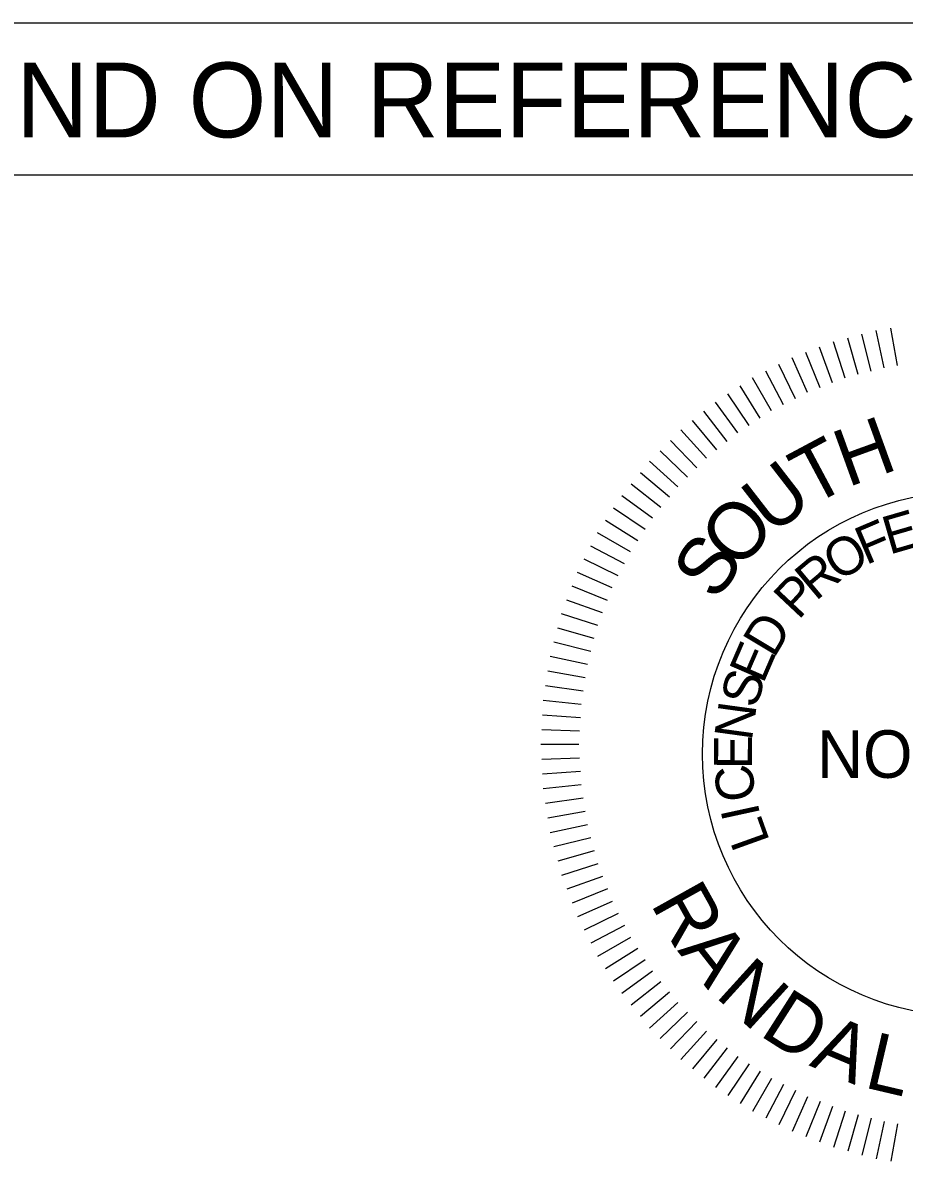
# Model space of a CAD drawing. Extents: x 1964377 to 1966966, y 1116414 to 1123213.
# Drawn here: x 1966782.8 to 1966865.3, y 1120286.7 to 1120393.2 of the extents above; entities that cross this region are included whole.
import ezdxf

# ---------------------------------------------------------------- set-up
doc = ezdxf.new("R2010")
doc.units = 0
doc.layers.add('RD_Sketch1', color=7, linetype='Continuous')
doc.layers.add('RD_TX_PEShield', color=7, linetype='Continuous')

msp = doc.modelspace()

# ---------------------------------------------------------------- linework, layer by layer
at = {"layer": 'RD_Sketch1'}
msp.add_lwpolyline([(1966615.77, 1120393.19), (1966916.19, 1120393.19), (1966916.19, 1120378.93), (1966615.77, 1120378.93)], close=True, dxfattribs=at)
at = {"layer": 'RD_TX_PEShield'}
for p, q in [((1966862.19, 1120360.61), (1966861.33, 1120364.06)), ((1966862.19, 1120360.61), (1966861.33, 1120364.06)), ((1966863.4, 1120360.93), (1966862.66, 1120364.41)), ((1966863.4, 1120360.93), (1966862.66, 1120364.41)), ((1966864.65, 1120361.13), (1966864.03, 1120364.63)), ((1966864.65, 1120361.13), (1966864.03, 1120364.63)), ((1966859.76, 1120359.96), (1966858.66, 1120363.34)), ((1966859.76, 1120359.96), (1966858.66, 1120363.34)), ((1966860.98, 1120360.28), (1966860, 1120363.7)), ((1966860.98, 1120360.28), (1966860, 1120363.7)), ((1966857.41, 1120359.06), (1966856.08, 1120362.35)), ((1966857.41, 1120359.06), (1966856.08, 1120362.35)), ((1966858.59, 1120359.51), (1966857.37, 1120362.85)), ((1966858.59, 1120359.51), (1966857.37, 1120362.85)), ((1966855.12, 1120358.03), (1966853.56, 1120361.23)), ((1966855.12, 1120358.03), (1966853.56, 1120361.23)), ((1966856.24, 1120358.6), (1966854.79, 1120361.86)), ((1966856.24, 1120358.6), (1966854.79, 1120361.86)), ((1966852.88, 1120356.89), (1966851.1, 1120359.97)), ((1966852.88, 1120356.89), (1966851.1, 1120359.97)), ((1966854, 1120357.46), (1966852.33, 1120360.6)), ((1966854, 1120357.46), (1966852.33, 1120360.6)), ((1966851.82, 1120356.21), (1966849.94, 1120359.22)), ((1966851.82, 1120356.21), (1966849.94, 1120359.22)), ((1966849.71, 1120354.84), (1966847.62, 1120357.72)), ((1966849.71, 1120354.84), (1966847.62, 1120357.72)), ((1966850.77, 1120355.52), (1966848.78, 1120358.47)), ((1966850.77, 1120355.52), (1966848.78, 1120358.47)), ((1966848.73, 1120354.04), (1966846.54, 1120356.85)), ((1966848.73, 1120354.04), (1966846.54, 1120356.85)), ((1966847.76, 1120353.25), (1966845.47, 1120355.98)), ((1966847.76, 1120353.25), (1966845.47, 1120355.98)), ((1966846.78, 1120352.46), (1966844.4, 1120355.11)), ((1966846.78, 1120352.46), (1966844.4, 1120355.11)), ((1966845.89, 1120351.57), (1966843.42, 1120354.13)), ((1966845.89, 1120351.57), (1966843.42, 1120354.13)), ((1966845, 1120350.68), (1966842.44, 1120353.15)), ((1966845, 1120350.68), (1966842.44, 1120353.15)), ((1966844.11, 1120349.79), (1966841.47, 1120352.18)), ((1966844.11, 1120349.79), (1966841.47, 1120352.18)), ((1966843.32, 1120348.82), (1966840.6, 1120351.1)), ((1966843.32, 1120348.82), (1966840.6, 1120351.1)), ((1966842.53, 1120347.84), (1966839.73, 1120350.03)), ((1966842.53, 1120347.84), (1966839.73, 1120350.03)), ((1966841.74, 1120346.86), (1966838.86, 1120348.95)), ((1966841.74, 1120346.86), (1966838.86, 1120348.95)), ((1966841.05, 1120345.81), (1966838.1, 1120347.8)), ((1966841.05, 1120345.81), (1966838.1, 1120347.8)), ((1966840.37, 1120344.75), (1966837.35, 1120346.64)), ((1966840.37, 1120344.75), (1966837.35, 1120346.64)), ((1966839.68, 1120343.7), (1966836.6, 1120345.48)), ((1966839.68, 1120343.7), (1966836.6, 1120345.48)), ((1966839.11, 1120342.58), (1966835.97, 1120344.25)), ((1966839.11, 1120342.58), (1966835.97, 1120344.25)), ((1966838.54, 1120341.46), (1966835.35, 1120343.02)), ((1966838.54, 1120341.46), (1966835.35, 1120343.02)), ((1966837.97, 1120340.34), (1966834.72, 1120341.78)), ((1966837.97, 1120340.34), (1966834.72, 1120341.78)), ((1966837.52, 1120339.16), (1966834.22, 1120340.49)), ((1966837.52, 1120339.16), (1966834.22, 1120340.49)), ((1966837.07, 1120337.99), (1966833.73, 1120339.2)), ((1966837.07, 1120337.99), (1966833.73, 1120339.2)), ((1966836.62, 1120336.81), (1966833.23, 1120337.91)), ((1966836.62, 1120336.81), (1966833.23, 1120337.91)), ((1966836.29, 1120335.6), (1966832.87, 1120336.58)), ((1966836.29, 1120335.6), (1966832.87, 1120336.58)), ((1966835.97, 1120334.38), (1966832.52, 1120335.25)), ((1966835.97, 1120334.38), (1966832.52, 1120335.25)), ((1966835.64, 1120333.17), (1966832.16, 1120333.91)), ((1966835.64, 1120333.17), (1966832.16, 1120333.91)), ((1966835.44, 1120331.93), (1966831.94, 1120332.54)), ((1966835.44, 1120331.93), (1966831.94, 1120332.54)), ((1966835.25, 1120330.69), (1966831.73, 1120331.18)), ((1966835.25, 1120330.69), (1966831.73, 1120331.18)), ((1966835.05, 1120329.44), (1966831.51, 1120329.82)), ((1966835.05, 1120329.44), (1966831.51, 1120329.82)), ((1966834.99, 1120328.19), (1966831.44, 1120328.43)), ((1966834.99, 1120328.19), (1966831.44, 1120328.43)), ((1966834.92, 1120326.93), (1966831.37, 1120327.06)), ((1966834.92, 1120326.93), (1966831.37, 1120327.06)), ((1966834.85, 1120325.68), (1966831.29, 1120325.68)), ((1966834.85, 1120325.68), (1966831.29, 1120325.68)), ((1966834.92, 1120324.42), (1966831.37, 1120324.29)), ((1966834.92, 1120324.42), (1966831.37, 1120324.29)), ((1966834.99, 1120323.16), (1966831.44, 1120322.92)), ((1966834.99, 1120323.16), (1966831.44, 1120322.92)), ((1966835.05, 1120321.91), (1966831.51, 1120321.54)), ((1966835.05, 1120321.91), (1966831.51, 1120321.54)), ((1966835.25, 1120320.67), (1966831.73, 1120320.17)), ((1966835.25, 1120320.67), (1966831.73, 1120320.17)), ((1966835.44, 1120319.42), (1966831.94, 1120318.81)), ((1966835.44, 1120319.42), (1966831.94, 1120318.81)), ((1966835.64, 1120318.18), (1966832.16, 1120317.44)), ((1966835.64, 1120318.18), (1966832.16, 1120317.44)), ((1966835.97, 1120316.97), (1966832.52, 1120316.11)), ((1966835.97, 1120316.97), (1966832.52, 1120316.11)), ((1966836.29, 1120315.75), (1966832.87, 1120314.77)), ((1966836.29, 1120315.75), (1966832.87, 1120314.77)), ((1966836.62, 1120314.54), (1966833.23, 1120313.44)), ((1966837.07, 1120313.36), (1966833.73, 1120312.15)), ((1966837.07, 1120313.36), (1966833.73, 1120312.15)), ((1966837.52, 1120312.19), (1966834.22, 1120310.86)), ((1966837.52, 1120312.19), (1966834.22, 1120310.86)), ((1966837.97, 1120311.01), (1966834.72, 1120309.57)), ((1966837.97, 1120311.01), (1966834.72, 1120309.57)), ((1966838.54, 1120309.89), (1966835.35, 1120308.33)), ((1966838.54, 1120309.89), (1966835.35, 1120308.33)), ((1966839.11, 1120308.77), (1966835.97, 1120307.1)), ((1966839.11, 1120308.77), (1966835.97, 1120307.1)), ((1966839.68, 1120307.65), (1966836.6, 1120305.87)), ((1966839.68, 1120307.65), (1966836.6, 1120305.87)), ((1966840.37, 1120306.6), (1966837.35, 1120304.71)), ((1966840.37, 1120306.6), (1966837.35, 1120304.71)), ((1966841.05, 1120305.54), (1966838.1, 1120303.56)), ((1966841.05, 1120305.54), (1966838.1, 1120303.56)), ((1966841.74, 1120304.49), (1966838.86, 1120302.4)), ((1966841.74, 1120304.49), (1966838.86, 1120302.4)), ((1966842.53, 1120303.51), (1966839.73, 1120301.32)), ((1966842.53, 1120303.51), (1966839.73, 1120301.32)), ((1966843.32, 1120302.53), (1966840.6, 1120300.25)), ((1966843.32, 1120302.53), (1966840.6, 1120300.25)), ((1966844.11, 1120301.56), (1966841.47, 1120299.17)), ((1966844.11, 1120301.56), (1966841.47, 1120299.17)), ((1966845, 1120300.67), (1966842.44, 1120298.2)), ((1966845, 1120300.67), (1966842.44, 1120298.2)), ((1966845.89, 1120299.78), (1966843.42, 1120297.22)), ((1966845.89, 1120299.78), (1966843.42, 1120297.22)), ((1966846.78, 1120298.89), (1966844.4, 1120296.24)), ((1966846.78, 1120298.89), (1966844.4, 1120296.24)), ((1966847.76, 1120298.1), (1966845.47, 1120295.37)), ((1966847.76, 1120298.1), (1966845.47, 1120295.37)), ((1966848.73, 1120297.31), (1966846.54, 1120294.5)), ((1966848.73, 1120297.31), (1966846.54, 1120294.5)), ((1966849.71, 1120296.51), (1966847.62, 1120293.63)), ((1966849.71, 1120296.51), (1966847.62, 1120293.63)), ((1966850.77, 1120295.83), (1966848.78, 1120292.88)), ((1966850.77, 1120295.83), (1966848.78, 1120292.88)), ((1966851.82, 1120295.14), (1966849.94, 1120292.13)), ((1966851.82, 1120295.14), (1966849.94, 1120292.13)), ((1966852.88, 1120294.46), (1966851.1, 1120291.38)), ((1966852.88, 1120294.46), (1966851.1, 1120291.38)), ((1966854, 1120293.89), (1966852.33, 1120290.75)), ((1966854, 1120293.89), (1966852.33, 1120290.75)), ((1966855.12, 1120293.32), (1966853.56, 1120290.12)), ((1966855.12, 1120293.32), (1966853.56, 1120290.12)), ((1966856.24, 1120292.75), (1966854.79, 1120289.49)), ((1966856.24, 1120292.75), (1966854.79, 1120289.49)), ((1966857.41, 1120292.3), (1966856.08, 1120289)), ((1966857.41, 1120292.3), (1966856.08, 1120289)), ((1966858.59, 1120291.85), (1966857.37, 1120288.5)), ((1966858.59, 1120291.85), (1966857.37, 1120288.5)), ((1966859.76, 1120291.39), (1966858.66, 1120288.01)), ((1966859.76, 1120291.39), (1966858.66, 1120288.01)), ((1966860.98, 1120291.07), (1966860, 1120287.65)), ((1966860.98, 1120291.07), (1966860, 1120287.65)), ((1966862.19, 1120290.74), (1966861.33, 1120287.29)), ((1966862.19, 1120290.74), (1966861.33, 1120287.29)), ((1966863.4, 1120290.42), (1966862.66, 1120286.94)), ((1966863.4, 1120290.42), (1966862.66, 1120286.94)), ((1966864.65, 1120290.22), (1966864.03, 1120286.72)), ((1966864.65, 1120290.22), (1966864.03, 1120286.72))]:
    msp.add_line(p, q, dxfattribs=at)
msp.add_circle((1966870.9, 1120324.8), 24.48, dxfattribs=at)

# ---------------------------------------------------------------- texts
at = {"layer": 'RD_Sketch1'}
msp.add_text('ALIGNMENT CONTROL CAN BE FOUND ON REFERENCE SHEET', height=7, dxfattribs=at).set_placement((1966619.42, 1120382.47))
at = {"layer": 'RD_TX_PEShield'}
for s, height, rotation, p in [('H', 5.34, 19.9102, (1966859.99, 1120349.72)), ('T', 5.34, 28.0947, (1966856.56, 1120347.91)), ('U', 5.34, 37.7726, (1966852.88, 1120345.17)), ('O', 5.34, 47.4504, (1966849.71, 1120341.85)), ('E', 3.56, 16.1843, (1966863.9, 1120343.43)), ('F', 3.56, 23.0853, (1966861.71, 1120342.45)), ('S', 5.34, 54.9027, (1966847.67, 1120338.96)), ('O', 3.56, 31.7869, (1966859.14, 1120340.86)), ('R', 3.56, 39.8902, (1966857, 1120339.04)), ('P', 3.56, 46.7912, (1966855.38, 1120337.27)), ('D', 3.56, 59.074, (1966853.09, 1120333.68)), ('E', 3.56, 66.5674, (1966852.08, 1120331.29)), ('S', 3.56, 73.4683, (1966851.44, 1120328.98)), ('N', 3.56, 82.17, (1966851.03, 1120325.98)), ('E', 3.56, 89.6633, (1966851.04, 1120323.38)), ('C', 3.56, 97.7667, (1966851.44, 1120320.6)), ('I', 3.56, 102.2511, (1966851.83, 1120319.09)), ('L', 3.56, 109.7445, (1966852.74, 1120316.65)), ('R', 5.34, 299.1493, (1966841.5, 1120310.82)), ('A', 5.34, 308.0877, (1966844.02, 1120306.42)), ('N', 5.34, 317.7655, (1966847.5, 1120302.17)), ('D', 5.34, 327.4433, (1966851.63, 1120298.56)), ('A', 5.34, 337.1212, (1966856.32, 1120295.69)), ('L', 5.34, 346.799, (1966861.42, 1120293.65))]:
    msp.add_text(s, height=height, rotation=rotation, dxfattribs=at).set_placement(p)
msp.add_text('NO. 24265', height=4.45, dxfattribs=at).set_placement((1966857.14, 1120322.57))

doc.saveas('drawing.dxf')
